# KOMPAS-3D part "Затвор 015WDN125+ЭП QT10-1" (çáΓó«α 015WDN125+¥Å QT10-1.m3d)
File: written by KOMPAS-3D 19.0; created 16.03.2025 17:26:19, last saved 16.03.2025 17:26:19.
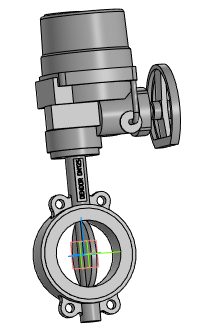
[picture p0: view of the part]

Document properties: Полное имя файла: Затвор 015WDN125+ЭП QT10-1.a3d

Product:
- Part/product: Затвор 015WDN125+ЭП QT10-1
    Масса: 49.4251

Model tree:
1. Операция без истории:1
